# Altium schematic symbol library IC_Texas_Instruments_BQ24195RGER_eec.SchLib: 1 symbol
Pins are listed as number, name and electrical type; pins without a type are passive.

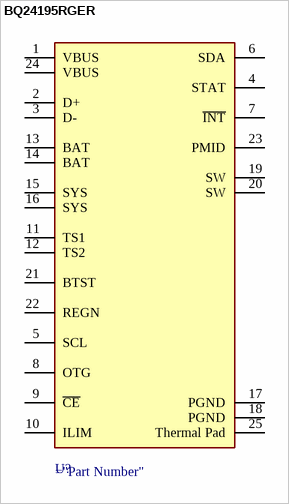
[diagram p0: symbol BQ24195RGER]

## BQ24195RGER
designator U?  (value not drawn)
pins: 1 VBUS, 2 D+, 3 D-, 4 STAT, 5 SCL, 6 SDA, 7 ~{INT}, 8 OTG, 9 ~{CE}, 10 ILIM, 11 TS1, 12 TS2, 13 BAT, 14 BAT, 15 SYS, 16 SYS, 17 PGND, 18 PGND, 19 SW, 20 SW, 21 BTST, 22 REGN, 23 PMID, 24 VBUS, 25 Thermal Pad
